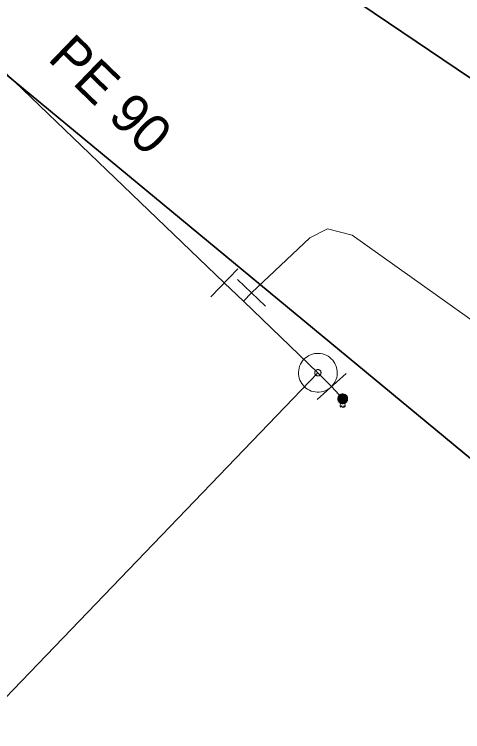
# Model space of a CAD drawing. Extents: x -779496 to -779026, y -977086 to -976624.
# Drawn here: x -779225.29 to -779213.73, y -976951.42 to -976932.93 of the extents above; entities that cross this region are included whole.
import ezdxf

# ---------------------------------------------------------------- set-up
doc = ezdxf.new("R2010")
doc.units = 0
doc.header["$LTSCALE"] = 0.4
doc.linetypes.add('MEDIUM_DASHED', pattern=[4.5, 3, -1.5])
for name, color, linetype, lineweight in [('1', 7, 'MEDIUM_DASHED', 25), ('13', 7, 'Continuous', 13), ('14', 7, 'Continuous', 13), ('17', 7, 'Continuous', 25), ('34', 7, 'Continuous', 13), ('47', 7, 'Continuous', 13), ('9', 7, 'Continuous', 13)]:
    doc.layers.add(name, color=color, linetype=linetype, lineweight=lineweight)

msp = doc.modelspace()

# ---------------------------------------------------------------- linework, layer by layer
at = {"layer": '13'}
msp.add_lwpolyline([(-779219.177, -976940.107), (-779217.669, -976938.688), (-779217.212, -976938.46), (-779216.583, -976938.617), (-779208.37, -976944.454)], dxfattribs=at)
at = {"layer": '14'}
for p, q in [((-779219.385, -976940.324), (-779219.177, -976940.107)), ((-779217.464, -976942.166), (-779217.109, -976942.519)), ((-779217.109, -976942.519), (-779216.823, -976942.838))]:
    msp.add_line(p, q, dxfattribs=at)
at = {"layer": '17'}
msp.add_line((-779219.879, -976939.85), (-779226.798, -976933.215), dxfattribs=at)
at = {"layer": '17', "lineweight": 35}
for points in [[(-779294.52, -976873.809), (-779286.179, -976884.319), (-779226.903, -976933.326), (-779213.28, -976944.579), (-779208.355, -976950.874)], [(-779283.847, -976885.578), (-779269.588, -976896.763), (-779267.93, -976897.881), (-779206.76, -976939.131), (-779203.521, -976944.031)]]:
    msp.add_lwpolyline(points, dxfattribs=at)
at = {"layer": '17'}
for points in [[(-779217.464, -976942.166), (-779219.385, -976940.324), (-779219.879, -976939.85)], [(-779251.16, -976976.582), (-779248.219, -976973.48), (-779233.02, -976958.26), (-779231.175, -976956.415), (-779231.048, -976956.283), (-779217.464, -976942.166)]]:
    msp.add_lwpolyline(points, dxfattribs=at)
at = {"layer": '34'}
for p, q in [((-779220.224, -976940.211), (-779219.532, -976939.489)), ((-779219.538, -976939.761), (-779218.816, -976940.453)), ((-779216.737, -976942.184), (-779217.481, -976942.852))]:
    msp.add_line(p, q, dxfattribs=at)
at = {"layer": '47'}
for points in [[(-779217.103, -976942.512), (-779217.069, -976942.472), (-779217.039, -976942.429), (-779217.014, -976942.383), (-779216.993, -976942.335), (-779216.978, -976942.285), (-779216.968, -976942.233), (-779216.965, -976942.181), (-779216.966, -976942.129), (-779216.972, -976942.077), (-779216.983, -976942.026), (-779217.001, -976941.976), (-779217.024, -976941.929), (-779217.05, -976941.885), (-779217.082, -976941.843), (-779217.117, -976941.805), (-779217.157, -976941.771), (-779217.2, -976941.741), (-779217.247, -976941.715), (-779217.294, -976941.695), (-779217.344, -976941.68), (-779217.396, -976941.67), (-779217.449, -976941.666), (-779217.501, -976941.667), (-779217.552, -976941.673), (-779217.603, -976941.685), (-779217.653, -976941.703), (-779217.7, -976941.725), (-779217.744, -976941.752), (-779217.786, -976941.784), (-779217.824, -976941.819), (-779217.858, -976941.859), (-779217.888, -976941.902), (-779217.914, -976941.948), (-779217.934, -976941.996), (-779217.949, -976942.046), (-779217.959, -976942.097), (-779217.964, -976942.15), (-779217.963, -976942.202), (-779217.956, -976942.254), (-779217.944, -976942.305), (-779217.926, -976942.355), (-779217.905, -976942.402), (-779217.877, -976942.446), (-779217.845, -976942.488), (-779217.81, -976942.526), (-779217.77, -976942.56), (-779217.727, -976942.59), (-779217.682, -976942.616), (-779217.633, -976942.636), (-779217.583, -976942.651), (-779217.532, -976942.661), (-779217.48, -976942.665), (-779217.428, -976942.664), (-779217.375, -976942.657), (-779217.324, -976942.646), (-779217.274, -976942.628), (-779217.228, -976942.606), (-779217.183, -976942.579), (-779217.141, -976942.547)], [(-779217.404, -976942.222), (-779217.398, -976942.216), (-779217.394, -976942.209), (-779217.39, -976942.201), (-779217.387, -976942.194), (-779217.384, -976942.185), (-779217.383, -976942.177), (-779217.381, -976942.168), (-779217.382, -976942.16), (-779217.383, -976942.151), (-779217.385, -976942.143), (-779217.388, -976942.134), (-779217.391, -976942.127), (-779217.396, -976942.12), (-779217.4, -976942.113), (-779217.407, -976942.106), (-779217.413, -976942.1), (-779217.42, -976942.096), (-779217.428, -976942.092), (-779217.435, -976942.089), (-779217.444, -976942.086), (-779217.452, -976942.085), (-779217.461, -976942.083), (-779217.469, -976942.084), (-779217.479, -976942.084), (-779217.486, -976942.087), (-779217.495, -976942.09), (-779217.502, -976942.093), (-779217.509, -976942.098), (-779217.516, -976942.102), (-779217.523, -976942.109), (-779217.529, -976942.115), (-779217.533, -976942.122), (-779217.537, -976942.13), (-779217.54, -976942.137), (-779217.543, -976942.146), (-779217.545, -976942.154), (-779217.546, -976942.163), (-779217.545, -976942.171), (-779217.545, -976942.181), (-779217.542, -976942.188), (-779217.539, -976942.197), (-779217.536, -976942.204), (-779217.531, -976942.211), (-779217.527, -976942.218), (-779217.52, -976942.225), (-779217.514, -976942.231), (-779217.507, -976942.235), (-779217.499, -976942.239), (-779217.492, -976942.242), (-779217.483, -976942.245), (-779217.475, -976942.247), (-779217.466, -976942.248), (-779217.458, -976942.247), (-779217.449, -976942.246), (-779217.441, -976942.244), (-779217.432, -976942.241), (-779217.425, -976942.238), (-779217.418, -976942.233), (-779217.411, -976942.229)]]:
    msp.add_lwpolyline(points, close=True, dxfattribs=at)
at = {"layer": '9'}
for points in [[(-779216.823, -976942.712), (-779216.836, -976942.711), (-779216.849, -976942.713), (-779216.862, -976942.716), (-779216.874, -976942.721), (-779216.886, -976942.727), (-779216.897, -976942.734), (-779216.907, -976942.742), (-779216.917, -976942.752), (-779216.925, -976942.762), (-779216.932, -976942.773), (-779216.938, -976942.785), (-779216.943, -976942.797), (-779216.946, -976942.81), (-779216.948, -976942.823), (-779216.95, -976942.836), (-779216.949, -976942.849), (-779216.947, -976942.862), (-779216.944, -976942.875), (-779216.939, -976942.887), (-779216.933, -976942.899), (-779216.926, -976942.91), (-779216.918, -976942.92), (-779216.908, -976942.93), (-779216.898, -976942.938), (-779216.887, -976942.945), (-779216.875, -976942.951), (-779216.863, -976942.956), (-779216.85, -976942.959), (-779216.837, -976942.961), (-779216.824, -976942.963), (-779216.811, -976942.963), (-779216.798, -976942.961), (-779216.785, -976942.958), (-779216.773, -976942.953), (-779216.761, -976942.947), (-779216.75, -976942.94), (-779216.74, -976942.932), (-779216.73, -976942.922), (-779216.722, -976942.912), (-779216.715, -976942.901), (-779216.709, -976942.889), (-779216.704, -976942.877), (-779216.701, -976942.864), (-779216.699, -976942.851), (-779216.698, -976942.838), (-779216.698, -976942.825), (-779216.7, -976942.812), (-779216.703, -976942.799), (-779216.708, -976942.787), (-779216.714, -976942.775), (-779216.721, -976942.764), (-779216.729, -976942.754), (-779216.739, -976942.744), (-779216.749, -976942.736), (-779216.76, -976942.729), (-779216.772, -976942.723), (-779216.784, -976942.718), (-779216.797, -976942.715), (-779216.81, -976942.713)], [(-779216.823, -976942.965), (-779216.81, -976942.964), (-779216.797, -976942.962), (-779216.784, -976942.959), (-779216.772, -976942.954), (-779216.76, -976942.948), (-779216.749, -976942.941), (-779216.739, -976942.933), (-779216.729, -976942.923), (-779216.721, -976942.913), (-779216.714, -976942.902), (-779216.708, -976942.89), (-779216.703, -976942.878), (-779216.7, -976942.865), (-779216.698, -976942.852), (-779216.697, -976942.839), (-779216.696, -976942.826), (-779216.698, -976942.813), (-779216.701, -976942.8), (-779216.706, -976942.788), (-779216.712, -976942.776), (-779216.719, -976942.765), (-779216.727, -976942.755), (-779216.737, -976942.745), (-779216.747, -976942.737), (-779216.758, -976942.73), (-779216.77, -976942.724), (-779216.782, -976942.719), (-779216.795, -976942.716), (-779216.808, -976942.714), (-779216.821, -976942.713), (-779216.834, -976942.713), (-779216.847, -976942.715), (-779216.86, -976942.718), (-779216.872, -976942.723), (-779216.884, -976942.729), (-779216.895, -976942.736), (-779216.905, -976942.744), (-779216.915, -976942.754), (-779216.923, -976942.764), (-779216.93, -976942.775), (-779216.936, -976942.787), (-779216.941, -976942.799), (-779216.944, -976942.812), (-779216.946, -976942.825), (-779216.949, -976942.838), (-779216.948, -976942.851), (-779216.946, -976942.864), (-779216.943, -976942.877), (-779216.938, -976942.889), (-779216.932, -976942.901), (-779216.925, -976942.912), (-779216.917, -976942.922), (-779216.907, -976942.932), (-779216.897, -976942.94), (-779216.886, -976942.947), (-779216.874, -976942.953), (-779216.862, -976942.958), (-779216.849, -976942.961), (-779216.836, -976942.963)], [(-779216.823, -976942.732), (-779216.834, -976942.73), (-779216.845, -976942.732), (-779216.856, -976942.735), (-779216.866, -976942.739), (-779216.876, -976942.744), (-779216.885, -976942.75), (-779216.894, -976942.757), (-779216.902, -976942.765), (-779216.909, -976942.774), (-779216.915, -976942.783), (-779216.92, -976942.793), (-779216.924, -976942.803), (-779216.927, -976942.814), (-779216.93, -976942.825), (-779216.93, -976942.836), (-779216.93, -976942.847), (-779216.928, -976942.858), (-779216.925, -976942.869), (-779216.921, -976942.879), (-779216.916, -976942.889), (-779216.91, -976942.898), (-779216.903, -976942.907), (-779216.895, -976942.915), (-779216.886, -976942.922), (-779216.877, -976942.928), (-779216.867, -976942.933), (-779216.857, -976942.937), (-779216.846, -976942.94), (-779216.835, -976942.942), (-779216.824, -976942.943), (-779216.813, -976942.944), (-779216.802, -976942.942), (-779216.791, -976942.939), (-779216.781, -976942.935), (-779216.771, -976942.93), (-779216.762, -976942.924), (-779216.753, -976942.917), (-779216.745, -976942.909), (-779216.738, -976942.9), (-779216.732, -976942.891), (-779216.727, -976942.881), (-779216.723, -976942.871), (-779216.72, -976942.86), (-779216.718, -976942.849), (-779216.718, -976942.838), (-779216.717, -976942.827), (-779216.719, -976942.816), (-779216.722, -976942.805), (-779216.726, -976942.795), (-779216.731, -976942.785), (-779216.737, -976942.776), (-779216.744, -976942.767), (-779216.752, -976942.759), (-779216.761, -976942.752), (-779216.77, -976942.746), (-779216.78, -976942.741), (-779216.79, -976942.737), (-779216.801, -976942.734), (-779216.812, -976942.732)], [(-779216.823, -976942.945), (-779216.812, -976942.945), (-779216.801, -976942.943), (-779216.79, -976942.94), (-779216.78, -976942.936), (-779216.77, -976942.931), (-779216.761, -976942.925), (-779216.752, -976942.918), (-779216.744, -976942.91), (-779216.737, -976942.901), (-779216.731, -976942.892), (-779216.726, -976942.882), (-779216.722, -976942.872), (-779216.719, -976942.861), (-779216.717, -976942.85), (-779216.717, -976942.839), (-779216.715, -976942.828), (-779216.717, -976942.817), (-779216.72, -976942.806), (-779216.724, -976942.796), (-779216.729, -976942.786), (-779216.735, -976942.777), (-779216.742, -976942.768), (-779216.75, -976942.76), (-779216.759, -976942.753), (-779216.768, -976942.747), (-779216.778, -976942.742), (-779216.788, -976942.738), (-779216.799, -976942.735), (-779216.81, -976942.733), (-779216.821, -976942.733), (-779216.832, -976942.732), (-779216.843, -976942.734), (-779216.854, -976942.737), (-779216.864, -976942.741), (-779216.874, -976942.746), (-779216.883, -976942.752), (-779216.892, -976942.759), (-779216.9, -976942.767), (-779216.907, -976942.776), (-779216.913, -976942.785), (-779216.918, -976942.795), (-779216.922, -976942.805), (-779216.925, -976942.816), (-779216.927, -976942.827), (-779216.929, -976942.838), (-779216.929, -976942.849), (-779216.927, -976942.86), (-779216.924, -976942.871), (-779216.92, -976942.881), (-779216.915, -976942.891), (-779216.909, -976942.9), (-779216.902, -976942.909), (-779216.894, -976942.917), (-779216.885, -976942.924), (-779216.876, -976942.93), (-779216.866, -976942.935), (-779216.856, -976942.939), (-779216.845, -976942.942), (-779216.834, -976942.944)], [(-779216.823, -976942.75), (-779216.832, -976942.75), (-779216.841, -976942.751), (-779216.85, -976942.754), (-779216.858, -976942.757), (-779216.866, -976942.761), (-779216.874, -976942.766), (-779216.881, -976942.772), (-779216.887, -976942.778), (-779216.893, -976942.785), (-779216.898, -976942.793), (-779216.902, -976942.801), (-779216.905, -976942.809), (-779216.908, -976942.818), (-779216.909, -976942.827), (-779216.911, -976942.836), (-779216.91, -976942.845), (-779216.909, -976942.854), (-779216.906, -976942.863), (-779216.903, -976942.871), (-779216.899, -976942.879), (-779216.894, -976942.887), (-779216.888, -976942.894), (-779216.882, -976942.9), (-779216.875, -976942.906), (-779216.867, -976942.911), (-779216.859, -976942.915), (-779216.851, -976942.918), (-779216.842, -976942.921), (-779216.833, -976942.922), (-779216.824, -976942.924), (-779216.815, -976942.924), (-779216.806, -976942.923), (-779216.797, -976942.92), (-779216.789, -976942.917), (-779216.781, -976942.913), (-779216.773, -976942.908), (-779216.766, -976942.902), (-779216.76, -976942.896), (-779216.754, -976942.889), (-779216.749, -976942.881), (-779216.745, -976942.873), (-779216.742, -976942.865), (-779216.739, -976942.856), (-779216.738, -976942.847), (-779216.737, -976942.838), (-779216.737, -976942.829), (-779216.738, -976942.82), (-779216.741, -976942.811), (-779216.744, -976942.803), (-779216.748, -976942.795), (-779216.753, -976942.787), (-779216.759, -976942.78), (-779216.765, -976942.774), (-779216.772, -976942.768), (-779216.78, -976942.763), (-779216.788, -976942.759), (-779216.796, -976942.756), (-779216.805, -976942.753), (-779216.814, -976942.752)], [(-779216.823, -976942.926), (-779216.814, -976942.925), (-779216.805, -976942.924), (-779216.796, -976942.921), (-779216.788, -976942.918), (-779216.78, -976942.914), (-779216.772, -976942.909), (-779216.765, -976942.903), (-779216.759, -976942.897), (-779216.753, -976942.89), (-779216.748, -976942.882), (-779216.744, -976942.874), (-779216.741, -976942.866), (-779216.738, -976942.857), (-779216.737, -976942.848), (-779216.736, -976942.839), (-779216.735, -976942.83), (-779216.736, -976942.821), (-779216.739, -976942.812), (-779216.742, -976942.804), (-779216.746, -976942.796), (-779216.751, -976942.788), (-779216.757, -976942.781), (-779216.763, -976942.775), (-779216.77, -976942.769), (-779216.778, -976942.764), (-779216.786, -976942.76), (-779216.794, -976942.757), (-779216.803, -976942.754), (-779216.812, -976942.753), (-779216.821, -976942.752), (-779216.83, -976942.752), (-779216.839, -976942.753), (-779216.848, -976942.756), (-779216.856, -976942.759), (-779216.864, -976942.763), (-779216.872, -976942.768), (-779216.879, -976942.774), (-779216.885, -976942.78), (-779216.891, -976942.787), (-779216.896, -976942.795), (-779216.9, -976942.803), (-779216.903, -976942.811), (-779216.906, -976942.82), (-779216.907, -976942.829), (-779216.91, -976942.838), (-779216.909, -976942.847), (-779216.908, -976942.856), (-779216.905, -976942.865), (-779216.902, -976942.873), (-779216.898, -976942.881), (-779216.893, -976942.889), (-779216.887, -976942.896), (-779216.881, -976942.902), (-779216.874, -976942.908), (-779216.866, -976942.913), (-779216.858, -976942.917), (-779216.85, -976942.92), (-779216.841, -976942.923), (-779216.832, -976942.924)], [(-779216.823, -976942.771), (-779216.83, -976942.77), (-779216.837, -976942.771), (-779216.844, -976942.772), (-779216.85, -976942.775), (-779216.856, -976942.778), (-779216.862, -976942.782), (-779216.868, -976942.786), (-779216.873, -976942.791), (-779216.877, -976942.797), (-779216.881, -976942.803), (-779216.884, -976942.809), (-779216.887, -976942.815), (-779216.888, -976942.822), (-779216.891, -976942.829), (-779216.891, -976942.836), (-779216.891, -976942.843), (-779216.889, -976942.85), (-779216.888, -976942.857), (-779216.885, -976942.863), (-779216.882, -976942.87), (-779216.878, -976942.875), (-779216.874, -976942.881), (-779216.869, -976942.886), (-779216.863, -976942.89), (-779216.857, -976942.894), (-779216.851, -976942.897), (-779216.845, -976942.9), (-779216.838, -976942.902), (-779216.831, -976942.903), (-779216.824, -976942.904), (-779216.817, -976942.905), (-779216.81, -976942.904), (-779216.803, -976942.902), (-779216.797, -976942.899), (-779216.79, -976942.896), (-779216.785, -976942.892), (-779216.779, -976942.888), (-779216.774, -976942.883), (-779216.77, -976942.877), (-779216.766, -976942.872), (-779216.763, -976942.865), (-779216.76, -976942.859), (-779216.758, -976942.852), (-779216.757, -976942.845), (-779216.757, -976942.838), (-779216.757, -976942.831), (-779216.757, -976942.824), (-779216.759, -976942.817), (-779216.762, -976942.811), (-779216.765, -976942.805), (-779216.769, -976942.799), (-779216.773, -976942.793), (-779216.778, -976942.788), (-779216.784, -976942.784), (-779216.789, -976942.78), (-779216.796, -976942.777), (-779216.802, -976942.774), (-779216.809, -976942.773), (-779216.816, -976942.771)], [(-779216.823, -976942.906), (-779216.816, -976942.906), (-779216.809, -976942.904), (-779216.802, -976942.903), (-779216.796, -976942.9), (-779216.79, -976942.897), (-779216.784, -976942.893), (-779216.778, -976942.889), (-779216.773, -976942.884), (-779216.769, -976942.878), (-779216.765, -976942.872), (-779216.762, -976942.866), (-779216.759, -976942.86), (-779216.758, -976942.853), (-779216.756, -976942.846), (-779216.756, -976942.839), (-779216.754, -976942.832), (-779216.756, -976942.825), (-779216.757, -976942.818), (-779216.76, -976942.812), (-779216.763, -976942.805), (-779216.767, -976942.8), (-779216.771, -976942.794), (-779216.776, -976942.789), (-779216.782, -976942.785), (-779216.788, -976942.781), (-779216.794, -976942.778), (-779216.8, -976942.775), (-779216.807, -976942.773), (-779216.814, -976942.772), (-779216.821, -976942.772), (-779216.828, -976942.771), (-779216.835, -976942.772), (-779216.842, -976942.774), (-779216.848, -976942.777), (-779216.855, -976942.78), (-779216.86, -976942.784), (-779216.866, -976942.788), (-779216.871, -976942.793), (-779216.875, -976942.799), (-779216.879, -976942.804), (-779216.882, -976942.811), (-779216.885, -976942.817), (-779216.887, -976942.824), (-779216.888, -976942.831), (-779216.89, -976942.838), (-779216.89, -976942.845), (-779216.889, -976942.852), (-779216.887, -976942.859), (-779216.884, -976942.865), (-779216.881, -976942.871), (-779216.877, -976942.877), (-779216.873, -976942.883), (-779216.868, -976942.888), (-779216.862, -976942.892), (-779216.857, -976942.896), (-779216.85, -976942.899), (-779216.844, -976942.902), (-779216.837, -976942.903), (-779216.83, -976942.905)], [(-779216.823, -976942.791), (-779216.828, -976942.79), (-779216.833, -976942.79), (-779216.838, -976942.791), (-779216.842, -976942.793), (-779216.847, -976942.795), (-779216.851, -976942.798), (-779216.854, -976942.801), (-779216.858, -976942.805), (-779216.861, -976942.808), (-779216.864, -976942.812), (-779216.866, -976942.817), (-779216.868, -976942.821), (-779216.869, -976942.826), (-779216.871, -976942.831), (-779216.871, -976942.836), (-779216.871, -976942.841), (-779216.87, -976942.846), (-779216.869, -976942.851), (-779216.867, -976942.855), (-779216.865, -976942.86), (-779216.862, -976942.864), (-779216.859, -976942.868), (-779216.855, -976942.871), (-779216.852, -976942.874), (-779216.848, -976942.877), (-779216.843, -976942.879), (-779216.839, -976942.881), (-779216.834, -976942.882), (-779216.829, -976942.883), (-779216.824, -976942.884), (-779216.819, -976942.885), (-779216.814, -976942.884), (-779216.809, -976942.883), (-779216.805, -976942.881), (-779216.8, -976942.879), (-779216.796, -976942.876), (-779216.792, -976942.873), (-779216.789, -976942.87), (-779216.786, -976942.866), (-779216.783, -976942.862), (-779216.781, -976942.857), (-779216.779, -976942.853), (-779216.778, -976942.848), (-779216.777, -976942.843), (-779216.777, -976942.838), (-779216.777, -976942.833), (-779216.778, -976942.828), (-779216.778, -976942.823), (-779216.78, -976942.819), (-779216.782, -976942.814), (-779216.785, -976942.81), (-779216.788, -976942.807), (-779216.791, -976942.803), (-779216.795, -976942.8), (-779216.799, -976942.797), (-779216.804, -976942.795), (-779216.808, -976942.793), (-779216.813, -976942.792), (-779216.818, -976942.791)], [(-779216.823, -976942.886), (-779216.818, -976942.886), (-779216.813, -976942.885), (-779216.808, -976942.884), (-779216.804, -976942.882), (-779216.799, -976942.88), (-779216.795, -976942.877), (-779216.792, -976942.874), (-779216.788, -976942.87), (-779216.785, -976942.867), (-779216.782, -976942.863), (-779216.78, -976942.858), (-779216.778, -976942.854), (-779216.777, -976942.849), (-779216.776, -976942.844), (-779216.776, -976942.839), (-779216.774, -976942.834), (-779216.775, -976942.829), (-779216.776, -976942.824), (-779216.778, -976942.82), (-779216.78, -976942.815), (-779216.783, -976942.811), (-779216.786, -976942.807), (-779216.79, -976942.804), (-779216.793, -976942.801), (-779216.797, -976942.798), (-779216.802, -976942.796), (-779216.806, -976942.794), (-779216.811, -976942.793), (-779216.816, -976942.792), (-779216.821, -976942.792), (-779216.826, -976942.791), (-779216.831, -976942.792), (-779216.836, -976942.793), (-779216.84, -976942.795), (-779216.845, -976942.797), (-779216.849, -976942.8), (-779216.853, -976942.803), (-779216.856, -976942.806), (-779216.859, -976942.81), (-779216.862, -976942.814), (-779216.864, -976942.819), (-779216.866, -976942.823), (-779216.867, -976942.828), (-779216.868, -976942.833), (-779216.87, -976942.838), (-779216.87, -976942.843), (-779216.869, -976942.848), (-779216.868, -976942.853), (-779216.866, -976942.857), (-779216.864, -976942.862), (-779216.861, -976942.866), (-779216.858, -976942.869), (-779216.855, -976942.873), (-779216.851, -976942.876), (-779216.847, -976942.879), (-779216.842, -976942.881), (-779216.838, -976942.883), (-779216.833, -976942.884), (-779216.828, -976942.885)], [(-779216.823, -976942.811), (-779216.826, -976942.81), (-779216.829, -976942.809), (-779216.831, -976942.81), (-779216.834, -976942.811), (-779216.837, -976942.812), (-779216.839, -976942.814), (-779216.841, -976942.816), (-779216.843, -976942.818), (-779216.845, -976942.82), (-779216.847, -976942.822), (-779216.849, -976942.825), (-779216.85, -976942.828), (-779216.85, -976942.83), (-779216.851, -976942.833), (-779216.851, -976942.836), (-779216.851, -976942.839), (-779216.851, -976942.842), (-779216.85, -976942.845), (-779216.849, -976942.847), (-779216.848, -976942.85), (-779216.846, -976942.852), (-779216.844, -976942.855), (-779216.842, -976942.857), (-779216.84, -976942.858), (-779216.838, -976942.86), (-779216.835, -976942.861), (-779216.832, -976942.863), (-779216.83, -976942.863), (-779216.827, -976942.864), (-779216.824, -976942.865), (-779216.821, -976942.865), (-779216.818, -976942.865), (-779216.815, -976942.864), (-779216.813, -976942.863), (-779216.81, -976942.862), (-779216.808, -976942.86), (-779216.805, -976942.859), (-779216.803, -976942.857), (-779216.802, -976942.854), (-779216.8, -976942.852), (-779216.799, -976942.849), (-779216.798, -976942.847), (-779216.797, -976942.844), (-779216.797, -976942.841), (-779216.796, -976942.838), (-779216.797, -976942.835), (-779216.796, -976942.832), (-779216.798, -976942.83), (-779216.798, -976942.827), (-779216.799, -976942.824), (-779216.801, -976942.822), (-779216.802, -976942.82), (-779216.804, -976942.818), (-779216.807, -976942.816), (-779216.809, -976942.814), (-779216.812, -976942.813), (-779216.814, -976942.812), (-779216.817, -976942.811), (-779216.82, -976942.811)], [(-779216.823, -976942.866), (-779216.82, -976942.866), (-779216.817, -976942.866), (-779216.815, -976942.865), (-779216.812, -976942.864), (-779216.809, -976942.863), (-779216.807, -976942.861), (-779216.805, -976942.859), (-779216.803, -976942.857), (-779216.801, -976942.855), (-779216.799, -976942.853), (-779216.798, -976942.85), (-779216.797, -976942.847), (-779216.796, -976942.845), (-779216.796, -976942.842), (-779216.796, -976942.839), (-779216.794, -976942.836), (-779216.794, -976942.833), (-779216.795, -976942.83), (-779216.796, -976942.828), (-779216.797, -976942.825), (-779216.799, -976942.823), (-779216.801, -976942.82), (-779216.803, -976942.818), (-779216.805, -976942.817), (-779216.807, -976942.815), (-779216.81, -976942.814), (-779216.813, -976942.813), (-779216.815, -976942.812), (-779216.818, -976942.812), (-779216.821, -976942.811), (-779216.824, -976942.811), (-779216.827, -976942.811), (-779216.83, -976942.812), (-779216.832, -976942.813), (-779216.835, -976942.814), (-779216.837, -976942.816), (-779216.84, -976942.817), (-779216.842, -976942.819), (-779216.843, -976942.822), (-779216.845, -976942.824), (-779216.846, -976942.827), (-779216.847, -976942.829), (-779216.848, -976942.832), (-779216.848, -976942.835), (-779216.851, -976942.838), (-779216.85, -976942.841), (-779216.85, -976942.844), (-779216.849, -976942.846), (-779216.848, -976942.849), (-779216.847, -976942.852), (-779216.845, -976942.854), (-779216.844, -976942.856), (-779216.842, -976942.858), (-779216.839, -976942.86), (-779216.837, -976942.862), (-779216.834, -976942.863), (-779216.832, -976942.864), (-779216.829, -976942.865), (-779216.826, -976942.865)], [(-779216.823, -976942.83), (-779216.825, -976942.829), (-779216.825, -976942.829), (-779216.825, -976942.83), (-779216.827, -976942.83), (-779216.828, -976942.829), (-779216.828, -976942.831), (-779216.828, -976942.831), (-779216.83, -976942.831), (-779216.83, -976942.831), (-779216.831, -976942.832), (-779216.831, -976942.834), (-779216.831, -976942.834), (-779216.832, -976942.834), (-779216.832, -976942.836), (-779216.832, -976942.836), (-779216.832, -976942.837), (-779216.832, -976942.838), (-779216.831, -976942.838), (-779216.831, -976942.839), (-779216.831, -976942.841), (-779216.83, -976942.841), (-779216.83, -976942.841), (-779216.829, -976942.842), (-779216.829, -976942.842), (-779216.828, -976942.844), (-779216.827, -976942.844), (-779216.826, -976942.845), (-779216.826, -976942.845), (-779216.825, -976942.845), (-779216.824, -976942.845), (-779216.823, -976942.846), (-779216.822, -976942.846), (-779216.822, -976942.846), (-779216.821, -976942.845), (-779216.82, -976942.845), (-779216.819, -976942.844), (-779216.819, -976942.844), (-779216.818, -976942.843), (-779216.818, -976942.843), (-779216.817, -976942.842), (-779216.817, -976942.841), (-779216.816, -976942.84), (-779216.816, -976942.84), (-779216.816, -976942.839), (-779216.816, -976942.838), (-779216.816, -976942.837), (-779216.816, -976942.836), (-779216.816, -976942.836), (-779216.817, -976942.835), (-779216.816, -976942.834), (-779216.818, -976942.833), (-779216.818, -976942.833), (-779216.818, -976942.832), (-779216.818, -976942.832), (-779216.82, -976942.831), (-779216.821, -976942.831), (-779216.822, -976942.831), (-779216.822, -976942.83), (-779216.823, -976942.83)], [(-779216.823, -976942.847), (-779216.822, -976942.847), (-779216.821, -976942.847), (-779216.821, -976942.846), (-779216.82, -976942.846), (-779216.819, -976942.846), (-779216.818, -976942.845), (-779216.818, -976942.845), (-779216.817, -976942.844), (-779216.817, -976942.844), (-779216.816, -976942.843), (-779216.816, -976942.842), (-779216.816, -976942.841), (-779216.815, -976942.841), (-779216.815, -976942.84), (-779216.815, -976942.839), (-779216.815, -976942.838), (-779216.815, -976942.837), (-779216.816, -976942.837), (-779216.815, -976942.836), (-779216.814, -976942.835), (-779216.815, -976942.834), (-779216.815, -976942.834), (-779216.816, -976942.833), (-779216.816, -976942.833), (-779216.817, -976942.832), (-779216.818, -976942.832), (-779216.819, -976942.831), (-779216.819, -976942.831), (-779216.82, -976942.831), (-779216.821, -976942.831), (-779216.822, -976942.831), (-779216.823, -976942.831), (-779216.823, -976942.831), (-779216.824, -976942.831), (-779216.825, -976942.831), (-779216.826, -976942.832), (-779216.826, -976942.832), (-779216.827, -976942.833), (-779216.827, -976942.833), (-779216.828, -976942.834), (-779216.828, -976942.835), (-779216.83, -976942.836), (-779216.83, -976942.836), (-779216.831, -976942.837), (-779216.831, -976942.838), (-779216.831, -976942.839), (-779216.831, -976942.84), (-779216.831, -976942.84), (-779216.83, -976942.841), (-779216.83, -976942.842), (-779216.829, -976942.843), (-779216.829, -976942.843), (-779216.828, -976942.844), (-779216.828, -976942.844), (-779216.827, -976942.845), (-779216.826, -976942.845), (-779216.825, -976942.845), (-779216.825, -976942.846), (-779216.824, -976942.846)]]:
    msp.add_lwpolyline(points, close=True, dxfattribs=at)
for points in [[(-779216.877, -976943.05), (-779216.889, -976943.024), (-779216.889, -976942.997), (-779216.877, -976942.971), (-779216.862, -976942.958)], [(-779216.85, -976943.02), (-779216.87, -976943.044), (-779216.877, -976943.05)], [(-779216.85, -976943.02), (-779216.84, -976943.046), (-779216.823, -976943.063)], [(-779216.796, -976943.02), (-779216.805, -976943.046), (-779216.823, -976943.063)], [(-779216.796, -976943.02), (-779216.776, -976943.044), (-779216.768, -976943.05)], [(-779216.768, -976943.05), (-779216.757, -976943.024), (-779216.757, -976942.997), (-779216.769, -976942.971), (-779216.783, -976942.958)]]:
    msp.add_lwpolyline(points, dxfattribs=at)

# ---------------------------------------------------------------- texts
at = {"layer": '1'}
msp.add_text('PE 90 ', height=1, rotation=316, dxfattribs=at).set_placement((-779224.461, -976934.09))

doc.saveas('drawing.dxf')
